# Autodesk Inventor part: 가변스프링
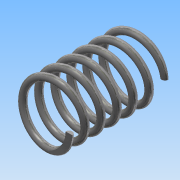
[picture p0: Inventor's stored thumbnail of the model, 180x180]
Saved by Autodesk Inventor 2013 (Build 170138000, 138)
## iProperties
Created: 2016-09
Part Number: 가변스프링
Material: 스테인리스강
Document SubType Name: Modeling
Designer: Administrator
Density: 1 g/cm^3
Author: Administrator
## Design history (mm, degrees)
sketch "스케치1"
  geometry: L1 (0, 0)-(8, 0); L2 (8, 0)-(8, 28.5); L3 (8, 28.5)-(0, 28.5); L4 (0, 28.5)-(0, 0); C1 r 1 at (8, 0)
  constraints: 8 end point, 2 parallel, 1 centre point, 1 coincident, 1 horizontal, 1 perpendicular
  dimensions: "d0" = 2 diameter of C1; "d3" = 16 diameter of L2 L4; "d4" = 28.5 distance of L1.end L2.end (derived)
feature "코일1" sketch "스케치1" pitch "d5" = 10; turns "d7" = 6; dims "d6" = 28.5 (= d4), "d8" = 0, angle "d9" = 90 deg, angle "d10" = 90 deg, "d11" = 0, "d12" = 0
sketch "스케치2"
  geometry: L1 (-9, 0)-(-7, 0) reference; 1 further point
  constraints: 1 horizontal alignment
extrude "돌출1" cut sketch "스케치2" distance "d13" = 10; taper "d14" = 0 deg
node "작업 평면1"
sketch "스케치3"
  geometry: L1 (1, 0)-(-1, 0) reference; 1 further point
  constraints: 1 horizontal alignment
extrude "돌출2" cut sketch "스케치3" distance "d16" = 10; taper "d17" = 0 deg
node "솔리드1"
node "절단 모서리 투영1"
node "절단 모서리 투영2"
other parameters: "d15" = 0
